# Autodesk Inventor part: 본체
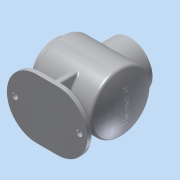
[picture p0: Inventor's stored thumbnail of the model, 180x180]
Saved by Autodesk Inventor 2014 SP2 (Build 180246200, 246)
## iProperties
Created: 2016-04
Part Number: 본체
Material: 알루미늄 6061
Document SubType Name: Modeling
Designer: SCD-A19
Density: 2.71 g/cm^3
Appearance: 알루미늄 - 평지
Mass: 909.903 g
Surface Area: 1227.61 cm^2
Volume: 335.757 cm^3
Author: SCD-A19
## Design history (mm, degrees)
sketch "스케치1"
  geometry: L1 (-55, 0)-(55, 0); L2 (-55, 0)-(-55, 50); L3 (-55, 50)-(44.087, 50); L4 (42.145, 47)-(-52, 47); L5 (-52, 47)-(-52, 0); L6 (-55, 0)-(55, 0); A1 r 120 centre (-65, 0) between (55, 0) and (44.087, 50); A2 r 117 centre (-65, 0) between (52, 0) and (42.145, 47); 2 further points
  constraints: 12 end point, 4 perpendicular, 4 point on circle, 2 centre point, 2 point on line, 1 coincident, 1 horizontal, 1 midpoint
  dimensions: "d1" = 100 diameter of L3 L1; "d64" = 110 distance from line of L1.end L2
revolve "회전1" stored, may be unused: angle "d2" = 90 deg
sketch "스케치2"
  geometry: C1 r 50 at (0, 0) reference; C2 r 38 at (0, 0)
  constraints: 1 centre point, 1 coincident
  dimensions: "d3" = 76 diameter of C2
extrude "돌출1" join sketch "스케치2" distance "d4" = 12; taper "d5" = 0 deg
node "작업 평면3"
sketch "스케치3"
  geometry: C1 r 38 at (5, 0); 1 further point
  constraints: 1 centre point
  dimensions: "d106" = 76 diameter of C1
extrude "돌출2" join sketch "스케치3" stored distance "d8" = 12; taper "d9" = 0 deg
sketch "스케치4"
  geometry: C1 r 38 at (-5, 0) reference; C2 r 27 at (-5, 0)
  constraints: 1 centre point, 1 coincident
  dimensions: "d107" = 54 diameter of C2
sketch "스케치5"
  geometry: C1 r 38 at (0, 0) reference; C2 r 27 at (0, 0)
  constraints: 1 centre point, 1 coincident
  dimensions: "d11" = 54 diameter of C2
extrude "돌출3" cut sketch "스케치5" distance "d12" = 15; taper "d13" = 0 deg
revolve "회전2" stored, may be unused: angle "d21" = 90 deg
fillet "모깎기1" dims "d24" = 2
sketch "스케치10" dims "d36" = 65
  geometry: C1 r 38 at (0, 0) reference; 2 further points
  constraints: 1 coincident, 1 vertical alignment, 2 other
hole "구멍2" sketch "스케치10" at (0, 32.5) diameter "d37" = 3.242; stored, may be unused: countersink angle "d41" = 90 deg, drill point angle "d43" = 118 deg; dims "d38" = 8, "d39" = 4, "d40" = 2, "d42" = 10
fillet "모깎기2" dims "d47" = 5
chamfer "모따기1" distance "d48" = 1; stored, may be unused: second distance "d49" = 2, angle "d50" = 45 deg
fillet "모깎기3" dims "d51" = 3
sketch "스케치13"
  geometry: L1 (-79, -50)-(-79, 50); L2 (0, 0)-(-69, 0); L3 (-69, -50)-(-69, 50); L4 (-69, 50)-(-79, 50); L5 (-69, -50)-(-79, -50); 1 further point
  constraints: 10 end point, 2 perpendicular, 1 horizontal alignment
  dimensions: "d60" = 69 distance of L2.start L2.end; "d61" = 100 distance of L3.start L3.end
extrude "돌출6" join sketch "스케치13" stored distance "d62" = 135; taper "d63" = 0 deg
sketch "스케치15"
  geometry: L1 (-69, -50)-(-69, 50) reference; L2 (-69, -40)-(-30, -40); L3 (0, 0)-(-69, 0); L4 (-69, 40)-(-30, 40); L5 (-69, -40)-(-69, 40); A1 r 50 centre (0, 0) between (50, 0) and (50, 0) reference; A2 r 50 centre (0, 0) between (-30, 40) and (-30, -40); 1 further point
  constraints: 8 end point, 3 point on circle, 2 symmetric about line, 1 centre point, 1 coincident, 1 collinear, 1 midpoint, 1 perpendicular, 1 point on line
extrude "돌출8" join sketch "스케치15" stored distance "d70" = 10; taper "d71" = 0 deg
sketch "스케치16"
  geometry: L1 (-50, -50)-(40.83, -50) reference; L2 (67.5, -69)-(-67.5, -69) reference; L3 (-36.65, -50)-(-40, -69); L4 (36.65, -50)-(40, -69); 1 further point
  constraints: 4 end point, 2 point on line
  dimensions: "d72" = 100 deg angle of L2 L3; "d73" = 40 horizontal distance of point (0, 0) L3.end
feature "리브1" dims "d74" = 1, "d75" = 10, "d76" = 0, "d77" = 0, "d78" = 1, "d79" = 1
feature "리브2" dims "d80" = 1, "d81" = 10, "d82" = 0, "d83" = 0, "d84" = 1, "d85" = 1
fillet "모깎기5" dims "d86" = 3
fillet "모깎기6" dims "d87" = 3
fillet "모깎기7" dims "d91" = 50
chamfer "모따기3" distance "d92" = 3; stored, may be unused: second distance "d93" = 2, angle "d94" = 45 deg
sketch "스케치17"
  geometry: L1 (35, 0)-(0, 0) reference; L2 (0, 94)-(35, 94) reference; L3 (-25.017, 55)-(-25.017, 39) reference; L4 (-25.017, 39)-(9.5, 39) reference; L5 (9.5, 39)-(9.5, 4) reference; L6 (9.5, 4)-(25.5, 4) reference; L7 (25.5, 4)-(25.5, 39) reference; L8 (25.5, 39)-(60.017, 39) reference; L9 (60.017, 39)-(60.017, 55) reference; L10 (60.017, 55)-(25.5, 55) reference; L11 (25.5, 55)-(25.5, 90) reference; L12 (25.5, 90)-(9.5, 90) reference; L13 (9.5, 90)-(9.5, 55) reference; L14 (9.5, 55)-(-25.017, 55) reference; L15 (17.5, 47)-(17.5, 66.457); C1 r 5 at (71.5, 47); A1 r 47 centre (0, 47) between (0, 94) and (0, 0) reference; A2 r 47 centre (35, 47) between (35, 0) and (35, 94) reference
  constraints: 2 end point, 1 centre point
  dimensions: "d95" = 10 diameter of C1; "d96" = 54 distance of C1.centre L15.start
extrude "돌출9" cut sketch "스케치17" stored distance "d97" = 10; taper "d98" = 0 deg
node "작업 평면7"
sketch "스케치18"
  geometry: 2 further points
  constraints: 1 coincident, 1 other
feature "엠보싱1" sketch "스케치18" dims "d1" = 100, "d64" = 110, "d100" = 0.5, "d101" = 0
extrude "돌출10" cut sketch "스케치4" stored distance "d108" = 10; taper "d109" = 0 deg
sketch "스케치19"
  geometry: 2 further points
hole "구멍3" sketch "스케치19" at (-32.5, 0) diameter "d111" = 3.242; stored, may be unused: countersink angle "d115" = 90 deg, drill point angle "d117" = 118 deg; dims "d112" = 8, "d113" = 4, "d114" = 2, "d116" = 10
fillet "모깎기8" dims "d121" = 3
node "솔리드1"
pattern_circular "원형 패턴2" dims angle "d45" = 360 deg
mirror "대칭1"
pattern_circular "원형 패턴3" dims angle "d119" = 360 deg
node "절단 모서리 투영1"
other parameters: "d6" = 65, "d99" = 63.5
